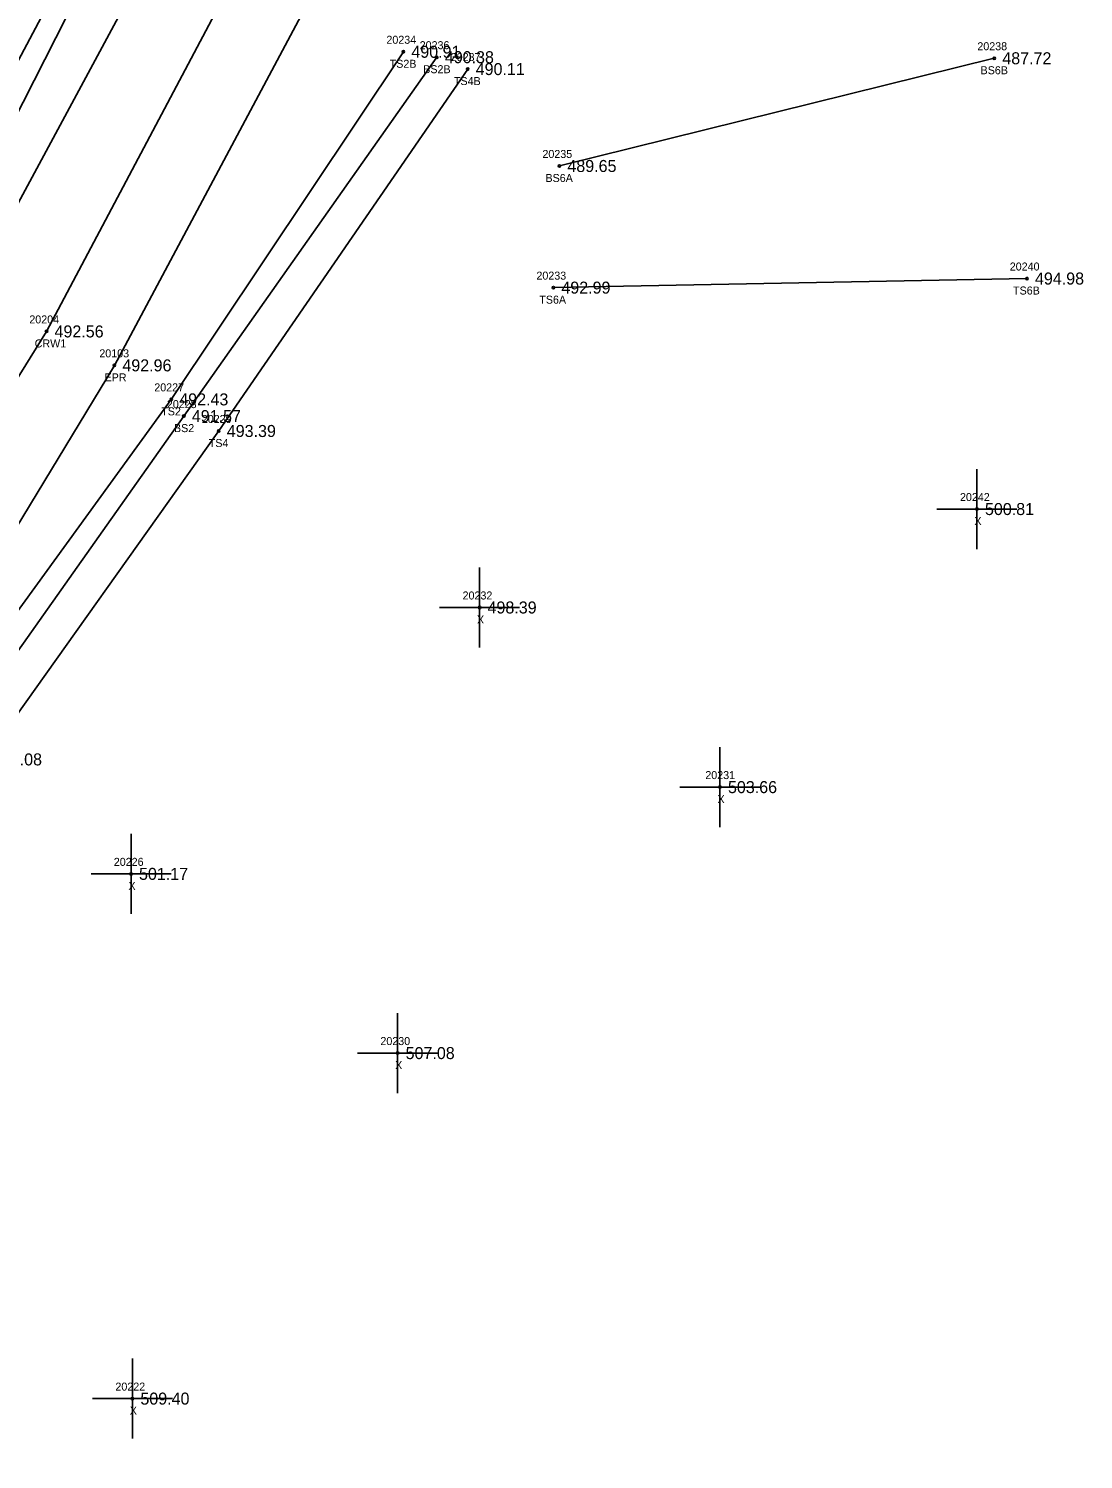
# Model space of a CAD drawing. Extents: x 1649406 to 1650436, y 896752 to 898178.
# Drawn here: x 1649795.4 to 1649927.2, y 897089.2 to 897267.9 of the extents above; entities that cross this region are included whole.
import ezdxf

# ---------------------------------------------------------------- set-up
doc = ezdxf.new("R2010")
doc.units = 0
for name, color, linetype in [('RD_DTM_BkLn1', 7, 'Continuous'), ('RD_DTM_BkLn2', 7, 'Continuous'), ('RD_DTM_BkLn_txCode', 7, 'Continuous'), ('RD_EX_Misc', 7, 'Continuous'), ('RD_EX_Misc_txCode', 7, 'Continuous'), ('RD_EX_Road', 7, 'Continuous'), ('RD_EX_Road_txCode', 7, 'Continuous'), ('RD_EX_TX_Misc_ELEV', 7, 'Continuous'), ('RD_EX_TX_Road_ELEV', 7, 'Continuous'), ('RD_HC_Survey_ELEV', 7, 'Continuous'), ('RD_HC_Survey_txCode', 7, 'Continuous'), ('RD_SMD_Locator', 7, 'Continuous')]:
    doc.layers.add(name, color=color, linetype=linetype)

msp = doc.modelspace()

# ---------------------------------------------------------------- linework, layer by layer
at = {"layer": 'RD_DTM_BkLn1'}
msp.add_lwpolyline([(1649466.79, 896799.14), (1649494.97, 896834.25), (1649557.53, 896909.97), (1649590.88, 896950.41), (1649622.36, 896988.16), (1649622.36, 896988.48), (1649654.33, 897027.92), (1649685.38, 897067.52), (1649715.96, 897107.48), (1649743.64, 897146.32), (1649771.01, 897187.23), (1649797.64, 897230.08), (1649820.89, 897273.98), (1649842.91, 897321.22), (1649862.74, 897368.05), (1649877.08, 897408.66)], dxfattribs=at)
at = {"layer": 'RD_DTM_BkLn2'}
for p, q in [((1649861.74, 897250.75), (1649916.1, 897264.21)), ((1649860.99, 897235.55), (1649920.18, 897236.69))]:
    msp.add_line(p, q, dxfattribs=at)
for points in [[(1649709.8, 897128.5), (1649729, 897156.36), (1649754.58, 897196.69), (1649780.91, 897239.21), (1649804.81, 897284.08), (1649825.46, 897331.72), (1649840.02, 897380.03), (1649851.88, 897417.91)], [(1649711.48, 897127.33), (1649731.83, 897154.08), (1649758, 897194.49), (1649783.81, 897237.31), (1649806.95, 897282.89), (1649830.65, 897328.8), (1649845.62, 897375.19), (1649854.76, 897409.92), (1649862.43, 897417.84), (1649895.58, 897416.19)], [(1649689.03, 896955.15), (1649675.54, 896986.1), (1649671.09, 897009.54), (1649678.93, 897030.09), (1649699.37, 897056.41), (1649730.7, 897097.01), (1649758.94, 897137.57), (1649785.6, 897178.21), (1649814.8, 897219.5), (1649846.42, 897264.34)], [(1649728.99, 897098.19), (1649756.58, 897138.53), (1649783.04, 897180.05), (1649813.23, 897221.59), (1649842.24, 897265.02)], [(1649692.17, 896958.45), (1649679.46, 896987.93), (1649676.76, 897009.49), (1649682.34, 897025.02), (1649708.77, 897048.86), (1649742.68, 897086.45), (1649767.3, 897132.79), (1649789.94, 897176.61), (1649819.17, 897217.64), (1649850.28, 897262.86)]]:
    msp.add_lwpolyline(points, dxfattribs=at)
at = {"layer": 'RD_EX_Misc'}
for p, q in [((1649913.93, 897202.89), (1649913.93, 897212.89)), ((1649908.93, 897207.89), (1649918.93, 897207.89)), ((1649851.76, 897190.59), (1649851.76, 897200.59)), ((1649846.76, 897195.59), (1649856.76, 897195.59)), ((1649881.81, 897168.15), (1649881.81, 897178.15)), ((1649876.81, 897173.15), (1649886.81, 897173.15)), ((1649808.2, 897157.31), (1649808.2, 897167.31)), ((1649803.2, 897162.31), (1649813.2, 897162.31)), ((1649841.52, 897134.92), (1649841.52, 897144.92)), ((1649836.52, 897139.92), (1649846.52, 897139.92)), ((1649808.37, 897091.75), (1649808.37, 897101.75)), ((1649803.37, 897096.75), (1649813.37, 897096.75))]:
    msp.add_line(p, q, dxfattribs=at)
at = {"layer": 'RD_EX_Road'}
for points in [[(1649459.38, 896805.71), (1649486.55, 896839.62), (1649513.65, 896873.34), (1649538.22, 896902.56), (1649549.43, 896916.62), (1649583.1, 896957.27), (1649614.8, 896995.02), (1649647.06, 897035.69), (1649677.62, 897074.51), (1649708.33, 897114.44), (1649735.5, 897151.61), (1649762.11, 897192.19), (1649788.21, 897235.29), (1649812.17, 897279.73), (1649834.32, 897326.54), (1649852.94, 897371.82), (1649867.51, 897411.96)], [(1649474.75, 896792.65), (1649502.78, 896827.35), (1649565.2, 896903.92), (1649598.28, 896943.71), (1649629.8, 896982.26), (1649667.92, 897029.33), (1649693.13, 897061.44), (1649723.58, 897101.84), (1649752.37, 897141.09), (1649779.72, 897182.3), (1649806.12, 897225.84), (1649830.13, 897270.79), (1649852.39, 897317.43), (1649871.98, 897364.35), (1649886.55, 897406.09)]]:
    msp.add_lwpolyline(points, dxfattribs=at)
at = {"layer": 'RD_SMD_Locator'}
for centre in [(1649842.24, 897265.02), (1649846.42, 897264.34), (1649916.1, 897264.21), (1649850.28, 897262.86), (1649861.74, 897250.75), (1649920.18, 897236.69), (1649860.99, 897235.55), (1649797.64, 897230.08), (1649806.12, 897225.84), (1649813.23, 897221.59), (1649814.8, 897219.5), (1649819.17, 897217.64), (1649913.93, 897207.89), (1649851.76, 897195.59), (1649881.81, 897173.15), (1649808.2, 897162.31), (1649841.52, 897139.92), (1649808.37, 897096.75)]:
    msp.add_circle(centre, 0.15, dxfattribs=at)

# ---------------------------------------------------------------- texts
at = {"layer": 'RD_DTM_BkLn_txCode'}
for s, p in [('20234', (1649840.12, 897266.02)), ('20236', (1649844.28, 897265.34)), ('20238', (1649913.98, 897265.21)), ('TS2B', (1649840.53, 897263.02)), ('20237', (1649848.16, 897263.86)), ('BS2B', (1649844.72, 897262.34)), ('TS4B', (1649848.56, 897260.86)), ('BS6B', (1649914.38, 897262.21)), ('20235', (1649859.62, 897251.75)), ('BS6A', (1649860, 897248.75)), ('20240', (1649918.03, 897237.69)), ('20233', (1649858.87, 897236.55)), ('TS6B', (1649918.44, 897234.69)), ('TS6A', (1649859.23, 897233.55)), ('20227', (1649811.11, 897222.59)), ('TS2', (1649811.98, 897219.59)), ('20228', (1649812.68, 897220.5)), ('20229', (1649817.05, 897218.64)), ('BS2', (1649813.57, 897217.5)), ('TS4', (1649817.92, 897215.64))]:
    msp.add_text(s, height=1, dxfattribs=at).set_placement(p)
at = {"layer": 'RD_EX_Misc_txCode'}
for s, p in [('20242', (1649911.81, 897208.89)), ('X', (1649913.61, 897205.89)), ('20232', (1649849.64, 897196.59)), ('X', (1649851.44, 897193.59)), ('20231', (1649879.98, 897174.15)), ('X', (1649881.5, 897171.15)), ('20226', (1649806.05, 897163.31)), ('X', (1649807.88, 897160.31)), ('20230', (1649839.37, 897140.92)), ('X', (1649841.21, 897137.92)), ('20222', (1649806.25, 897097.75)), ('X', (1649808.05, 897094.75))]:
    msp.add_text(s, height=1, dxfattribs=at).set_placement(p)
at = {"layer": 'RD_EX_Road_txCode'}
for s, p in [('20103', (1649804.24, 897226.84)), ('EPR', (1649804.89, 897223.84))]:
    msp.add_text(s, height=1, dxfattribs=at).set_placement(p)
at = {"layer": 'RD_EX_TX_Misc_ELEV'}
for s, p in [('490.91', (1649843.24, 897264.27)), ('490.38', (1649847.42, 897263.59)), ('490.11', (1649851.28, 897262.11)), ('487.72', (1649917.1, 897263.46)), ('489.65', (1649862.74, 897250)), ('494.98', (1649921.18, 897235.94)), ('492.99', (1649861.99, 897234.8)), ('492.43', (1649814.23, 897220.84)), ('491.57', (1649815.8, 897218.75)), ('493.39', (1649820.17, 897216.89)), ('500.81', (1649914.93, 897207.14)), ('498.39', (1649852.76, 897194.84)), ('496.08', (1649790.94, 897175.86)), ('503.66', (1649882.81, 897172.4)), ('501.17', (1649809.2, 897161.56)), ('507.08', (1649842.52, 897139.17)), ('509.40', (1649809.37, 897096))]:
    msp.add_text(s, height=1.5, dxfattribs=at).set_placement(p)
at = {"layer": 'RD_EX_TX_Road_ELEV'}
msp.add_text('492.96', height=1.5, dxfattribs=at).set_placement((1649807.12, 897225.09))
at = {"layer": 'RD_HC_Survey_ELEV'}
msp.add_text('492.56', height=1.5, dxfattribs=at).set_placement((1649798.64, 897229.33))
at = {"layer": 'RD_HC_Survey_txCode'}
for s, p in [('20204', (1649795.49, 897231.08)), ('CRW1', (1649796.16, 897228.08))]:
    msp.add_text(s, height=1, dxfattribs=at).set_placement(p)

doc.saveas('drawing.dxf')
